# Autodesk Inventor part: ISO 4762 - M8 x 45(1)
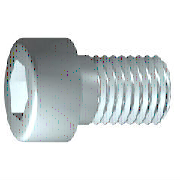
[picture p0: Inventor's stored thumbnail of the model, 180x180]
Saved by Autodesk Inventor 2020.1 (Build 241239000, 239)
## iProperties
Created: 2019-01
Part Number: ISO 4762 - M8 x 45(1)
Material: Edelstahl, 440C
Description: Innensechskantschraube
Document SubType Name: Modeling
Standard: ISO 4762
Designer: lutzd
Standard Revision: Fourth edition 2004-03-01
Standards Organization: ISO
Language: de-DE
Size Designation: M8 x 45
Categories: <MemberInstance><Categories><Category DisplayName="Verbindungselemente" InternalName="e4da775c-781d-43d5-af7c-5136215cf5a6" Mnemonic="FSTN"><Category DisplayNam
Mass: 24.5081 g
Surface Area: 17.8735 cm^2
Volume: 3.16234 cm^3
Density: 7.75 g/cm^3
Appearance: Semi-Polished(3)
IsCustomPart: 0
Author: lutzd
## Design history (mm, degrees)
workplane "Work Plane1"
fillet "Fillet2" dims "d30" = 0.1 (= R)
sketch "Skizze1"
  geometry: L1 (-2, 0)-(45, 0); L2 (45, 0)-(45, 4); L3 (45, 4)-(17, 4); L4 (17, 4)-(16.233, 4); L5 (16.233, 4)-(0, 4); L6 (0, 4)-(0, 6.5); L7 (0, 6.5)-(-8, 6.5); L8 (-8, 6.5)-(-8, 3.464); L9 (-8, 3.464)-(-4, 3.464); L10 (-4, 3.464)-(-2, 0); L11 (-18.6, 0)-(55.6, 0) reference; L12 (0, -1.3)-(0, 7.8) reference; L13 (17, 4)-(0, 4)
  constraints: 22 end point, 6 parallel, 2 collinear, 2 perpendicular, 1 horizontal, 1 point on line
  dimensions: "d1" = 28 distance from line of L3.end L2 (= GEL); "d2" = 0.76691 distance of L4.end L3.end (computed from GAL); "d3" = 8 distance between parallel lines of L8 L6 (= KOH); "d4" = 4 distance of L8.end L9.end (= INTI); "d5" = 60 deg angle of L10 L1; "d6" = 8 diameter of L3 L1 (= GD); "d7" = 8 diameter of L5 L1 (= BDM); "d8" = 6.9282 diameter of L9 L1 (= 1.1547 x SW); "d9" = 13 diameter of L7 L1 (= KOD); "d26" = 45 distance between parallel lines of L12 L2 (= NLG)
revolve "Körper" sketch "Skizze1" stored, may be unused: angle "d10" = 90 deg
sketch "Skizze2"
  geometry: L1 (0, -9.1)-(0, 9.1) reference; L2 (-9.1, 0)-(9.1, 0) reference; L3 (3.464, 0)-(1.732, -3); L4 (1.732, -3)-(-1.732, -3); L5 (-1.732, -3)-(-3.464, 0); L6 (-3.464, 0)-(-1.732, 3); L7 (-1.732, 3)-(1.732, 3); L8 (1.732, 3)-(3.464, 0); 2 further points
  constraints: 12 end point, 1 coincident, 1 horizontal alignment, 1 point on line, 12 other
extrude "Loch" join sketch "Skizze2" stored distance "d11" = 10; taper "d12" = 0 deg
body "Solid1"
fillet "Rundung1" dims "d17" = 0.8 (= RR)
feature "Gewinde" dims "d13" = 28 (= GEL), "d14" = 0
chamfer "Fase1" distance "d15" = 0.76681 (= -0.5 x SPD + 0.5 x GD); stored, may be unused: second distance "d16" = 0.76681 (= GUL), angle "d27" = 45 deg
other parameters: "GD" = 8 [user parameter; used in 2 equation terms], "NLG" = 45 [user parameter; used in 1 equation term], "GEL" = 28 [user parameter; used in 2 equation terms], "KOD" = 13 [user parameter; used in 1 equation term], "KOH" = 8 [user parameter; used in 1 equation term], "INTI" = 4 [user parameter; used in 1 equation term], "GAL" = 0.76681 (= 0.61345 x PTC) [user parameter; used in 1 equation term], "GUL" = 0.76681 (= 0.61345 x PTC) [user parameter; used in 1 equation term], "BDM" = 8 (= NND) [user parameter; used in 1 equation term], "SW" = 6 [user parameter; used in 2 equation terms], "RR" = 0.8 [user parameter; used in 1 equation term], "SPD" = 6.46637 (= NND - 1.2269 x PTC) [user parameter; used in 1 equation term], "d19" = 0, "d28" = 0, "d29" = 0, "R" = 0.1 [user parameter; used in 1 equation term], "TOA" = 30 deg [user parameter], "GD1" = 6.46637 (= THREADDIA - 1.2269 x PTC) [user parameter], "THREADDIA" = 8 [user parameter; used in 1 equation term], "FAWI" = 45 deg [user parameter], "TPU" = 8 (computed from PTC) [user parameter], "PTC" = 1.25 [user parameter; used in 5 equation terms], "NND" = 8 [user parameter; used in 2 equation terms], "E0" = 6.93 (= 1.155 x SW) [user parameter]
